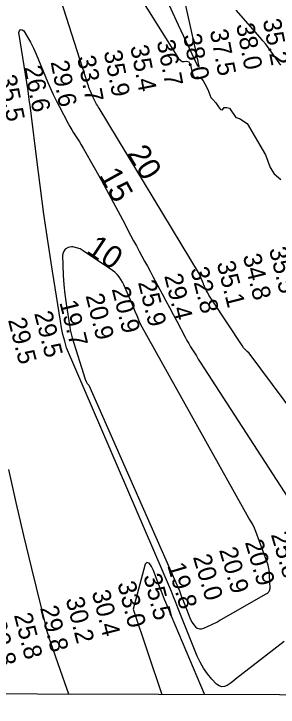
# Model space of a CAD drawing. Extents: x 3161665 to 3199565, y 885729 to 911164.
# Drawn here: x 3179674 to 3180653, y 891109 to 893674 of the extents above; entities that cross this region are included whole.
import ezdxf

# ---------------------------------------------------------------- set-up
doc = ezdxf.new("R2010")
doc.units = 0
for name, color, linetype in [('V-GRID-FRAM', 7, 'Continuous'), ('V-RIVR-RANG', 7, 'Continuous'), ('V-SITE-VEGE', 7, 'Continuous'), ('V-TOPO-DPTH', 7, 'Continuous'), ('V-TOPO-MAJR', 7, 'Continuous'), ('V-TOPO-MINR', 7, 'Continuous'), ('V-TOPO-MINR-IDEN', 7, 'Continuous'), ('V-WETL-SWMP', 7, 'Continuous')]:
    doc.layers.add(name, color=color, linetype=linetype)

msp = doc.modelspace()

# ---------------------------------------------------------------- linework, layer by layer
at = {"layer": 'V-GRID-FRAM'}
msp.add_lwpolyline([(3165935.6, 909383.8), (3197271.3, 909297.2), (3197229, 891108.8), (3165877.4, 891195.5), (3165935.6, 909383.8)], dxfattribs=at)
at = {"layer": 'V-SITE-VEGE'}
for p, q in [((3180093.9, 893811.8), (3180283.7, 893509.1)), ((3180283.7, 893509.1), (3180293.5, 893500.4)), ((3180293.5, 893500.4), (3180297.8, 893498.2)), ((3180297.8, 893498.2), (3180304.3, 893498.2)), ((3180304.3, 893498.2), (3180313, 893499.3)), ((3180313, 893499.3), (3180321.7, 893496)), ((3180321.7, 893496), (3180328.2, 893484.1)), ((3180328.2, 893484.1), (3180331.4, 893467.8)), ((3180331.4, 893467.8), (3180338, 893445)), ((3180338, 893445), (3180343.4, 893437.4)), ((3180343.4, 893437.4), (3180354.2, 893440.7)), ((3180354.2, 893440.7), (3180365.1, 893438.5)), ((3180365.1, 893438.5), (3180374.8, 893425.5)), ((3180374.8, 893425.5), (3180381.3, 893414.6)), ((3180381.3, 893414.6), (3180392.2, 893394)), ((3180392.2, 893394), (3180403, 893364.7)), ((3180403, 893364.7), (3180410.6, 893357.1)), ((3180410.6, 893357.1), (3180422.6, 893344.1)), ((3180422.6, 893344.1), (3180432.3, 893330)), ((3180432.3, 893330), (3180438.8, 893320.2)), ((3180446.4, 893319.2), (3180452.9, 893327.8)), ((3180452.9, 893327.8), (3180462.7, 893327.8)), ((3180462.7, 893327.8), (3180472.5, 893324.6)), ((3180438.8, 893320.2), (3180446.4, 893319.2)), ((3180472.5, 893324.6), (3180496.3, 893290.9)), ((3180496.3, 893290.9), (3180509.4, 893286.6)), ((3180509.4, 893286.6), (3180538.1, 893268)), ((3180538.1, 893268), (3180606.4, 893152.6)), ((3180606.4, 893152.6), (3180623.5, 893105.6)), ((3180623.5, 893105.6), (3180638.5, 893082.1)), ((3180638.5, 893082.1), (3180662, 893060.7))]:
    msp.add_line(p, q, dxfattribs=at)
at = {"layer": 'V-TOPO-DPTH'}
msp.add_lwpolyline([(3179885, 892494.7), (3179887.6, 892484.8), (3179890.4, 892475), (3179938.7, 892322.2), (3179942.1, 892314.1), (3179946.2, 892306.6), (3179951.5, 892299.8), (3180287.6, 891539.2), (3180290.2, 891531.8), (3180292.8, 891524.5), (3180295.5, 891517.3), (3180298.3, 891510), (3180325.6, 891439.3), (3180329.7, 891430.4), (3180334.4, 891421.8), (3180340.1, 891413.9), (3180346.3, 891406.3), (3180353.5, 891401.2), (3180361.1, 891398.2), (3180369.2, 891398.3), (3180377.7, 891400.4), (3180425.3, 891423.3), (3180429.5, 891425.5), (3180433.5, 891427.8), (3180437.4, 891430.3), (3180441.3, 891433), (3180607.9, 891528.5), (3180611, 891529.8), (3180614, 891531.5), (3180616.5, 891533.8), (3180618.7, 891536.4), (3180620.4, 891539.4), (3180621.6, 891542.6), (3180622.3, 891545.9), (3180622.5, 891549.4), (3180621.2, 891595.7), (3180620.2, 891608.8), (3180618.4, 891621.8), (3180615.2, 891634.5), (3180611.3, 891647.1), (3180569.9, 891758.7), (3180564.6, 891771.6), (3180558.6, 891784.2), (3180551.7, 891796.4), (3180544.2, 891808.2), (3180142.8, 892525.3), (3180136.7, 892541.1), (3180130.4, 892556.8), (3180124, 892572.5), (3180117.4, 892588.1), (3180086.3, 892660.5), (3180081.4, 892671), (3180076.1, 892681.3), (3180070.2, 892691.2), (3180063.8, 892700.9), (3180056.6, 892709.8), (3180048.7, 892717.9), (3180039.7, 892724.8), (3179931.6, 892797), (3179919.8, 892804.3), (3179906.7, 892808.8), (3179892.7, 892811.5), (3179888.4, 892811.8), (3179875.2, 892809.2), (3179864.8, 892803.6), (3179858.6, 892793.6), (3179855.1, 892780.7), (3179855.6, 892743.1), (3179856.8, 892707.4), (3179859, 892671.8), (3179862.8, 892636.4), (3179867.6, 892601), (3179881.1, 892514.7), (3179882.9, 892504.6), (3179885, 892494.7)], dxfattribs=at)
at = {"layer": 'V-TOPO-MAJR'}
for points in [[(3180209, 894161.2), (3180349, 893526.9), (3180350.6, 893519.5), (3180352.3, 893512), (3180353.9, 893504.5), (3180355.6, 893497), (3180358.4, 893484.2), (3180358.6, 893483.1), (3180358.6, 893479.9), (3180358.2, 893477.1), (3180358, 893476.9)], [(3180358, 893476.9), (3180357.9, 893476.8), (3180357.8, 893476.8), (3180357.6, 893476.9), (3180357.3, 893477.2), (3180355, 893481.3), (3180354.6, 893482.1), (3180354.2, 893482.9), (3180283.4, 893631.5), (3180249.6, 893707.4)]]:
    msp.add_lwpolyline(points, dxfattribs=at)
at = {"layer": 'V-TOPO-MINR'}
for points in [[(3181020.6, 891780.5), (3180544.9, 892418.5), (3180537.8, 892424.8), (3180531, 892431.5), (3180524.9, 892438.8), (3180519.3, 892446.5), (3180410.3, 892610.3), (3180405.4, 892617.8), (3180400.7, 892625.5), (3180396.2, 892633.4), (3180391.8, 892641.3), (3180387.7, 892649.3), (3180383.8, 892657.5), (3180380.1, 892665.7), (3180376.6, 892674), (3180376.3, 892675), (3180372.7, 892683.9), (3180369, 892692.7), (3180365.2, 892701.5), (3180361.4, 892710.2), (3179989.9, 893325.5), (3179986.8, 893330.1), (3179983.7, 893334.8), (3179980.8, 893339.5), (3179977.9, 893344.3), (3179975.1, 893349.2), (3179972.5, 893354.1), (3179970.1, 893359.2), (3179967.8, 893364.3), (3179957, 893389.9), (3179954.7, 893395.7), (3179952.4, 893401.5), (3179950.3, 893407.3), (3179948.4, 893413.3), (3179820.1, 893816)], [(3180674.6, 891351.6), (3180494.7, 891212.8), (3180485.1, 891204.2), (3180474.9, 891196.4), (3180464.3, 891189), (3180453.8, 891185.3), (3180443.7, 891184.4), (3180434.1, 891187.8), (3180424.9, 891194), (3180407.6, 891212.7), (3180391.3, 891232.3), (3180376.6, 891252.8), (3180364.3, 891274.9), (3180353.5, 891298), (3180281.9, 891475.7), (3180273.8, 891496.1), (3180265.9, 891516.5), (3180258.2, 891537.1), (3179869.9, 892438.1), (3179862.7, 892462.7), (3179856.3, 892487.4), (3179851, 892512.4), (3179846.5, 892537.5), (3179817.5, 892721.4), (3179801.4, 892827.2), (3179786, 892933.1), (3179771.7, 893039.1), (3179758.2, 893145.3), (3179739.8, 893295), (3179735.8, 893326.3), (3179731.6, 893357.6), (3179727, 893388.9), (3179722.3, 893420.1), (3179693.1, 893604.7), (3179695.8, 893611.7), (3179699.6, 893615.8), (3179705.1, 893615.3), (3179711.8, 893611.7), (3179724.3, 893590.7), (3179736.2, 893569.3), (3179746.9, 893547.3), (3179756.8, 893524.9), (3179800.2, 893419.7), (3179809.8, 893397.5), (3179819.8, 893375.4), (3179830.5, 893353.6), (3179841.6, 893332.1), (3179875.7, 893268.2), (3179882.1, 893256.6), (3179888.7, 893245.1), (3179895.6, 893233.8), (3179902.7, 893222.7), (3179909.9, 893211.5), (3179916.9, 893200.3), (3179923.7, 893188.9), (3179930.4, 893177.4), (3179971.6, 893105.4), (3179998.4, 893057.7), (3180024.9, 893009.8), (3180050.9, 892961.6), (3180076.5, 892913.3), (3180107.9, 892853.1), (3180117.9, 892834.2), (3180127.9, 892815.3), (3180138.1, 892796.5), (3180148.3, 892777.7), (3180158.6, 892759), (3180168.8, 892740.2), (3180178.9, 892721.4), (3180189, 892702.5), (3180223.5, 892637.8), (3180236.9, 892612.5), (3180250.3, 892587.3), (3180263.8, 892562), (3180277.2, 892536.8), (3180308.7, 892477.6), (3180315.2, 892465.8), (3180321.8, 892454.1), (3180328.7, 892442.5), (3180335.8, 892431.1), (3180343, 892419.7), (3180350, 892408.3), (3180357, 892396.7), (3180363.9, 892385.2), (3180744.9, 891797.1)], [(3179885, 892494.7), (3179887.6, 892484.8), (3179890.4, 892475), (3179938.7, 892322.2), (3179942.1, 892314.1), (3179946.2, 892306.6), (3179951.5, 892299.8), (3180287.6, 891539.2), (3180290.2, 891531.8), (3180292.8, 891524.5), (3180295.5, 891517.3), (3180298.3, 891510), (3180325.6, 891439.3), (3180329.7, 891430.4), (3180334.4, 891421.8), (3180340.1, 891413.9), (3180346.3, 891406.3), (3180353.5, 891401.2), (3180361.1, 891398.2), (3180369.2, 891398.3), (3180377.7, 891400.4), (3180425.3, 891423.3), (3180429.5, 891425.5), (3180433.5, 891427.8), (3180437.4, 891430.3), (3180441.3, 891433), (3180607.9, 891528.5), (3180611, 891529.8), (3180614, 891531.5), (3180616.5, 891533.8), (3180618.7, 891536.4), (3180620.4, 891539.4), (3180621.6, 891542.6), (3180622.3, 891545.9), (3180622.5, 891549.4), (3180621.2, 891595.7), (3180620.2, 891608.8), (3180618.4, 891621.8), (3180615.2, 891634.5), (3180611.3, 891647.1), (3180569.9, 891758.7), (3180564.6, 891771.6), (3180558.6, 891784.2), (3180551.7, 891796.4), (3180544.2, 891808.2), (3180142.8, 892525.3), (3180136.7, 892541.1), (3180130.4, 892556.8), (3180124, 892572.5), (3180117.4, 892588.1), (3180086.3, 892660.5), (3180081.4, 892671), (3180076.1, 892681.3), (3180070.2, 892691.2), (3180063.8, 892700.9), (3180056.6, 892709.8), (3180048.7, 892717.9), (3180039.7, 892724.8), (3179931.6, 892797), (3179919.8, 892804.3), (3179906.7, 892808.8), (3179892.7, 892811.5), (3179888.4, 892811.8), (3179875.2, 892809.2), (3179864.8, 892803.6), (3179858.6, 892793.6), (3179855.1, 892780.7), (3179855.6, 892743.1), (3179856.8, 892707.4), (3179859, 892671.8), (3179862.8, 892636.4), (3179867.6, 892601), (3179881.1, 892514.7), (3179882.9, 892504.6), (3179885, 892494.7)], [(3179878.4, 891156.8), (3179870.5, 891177.9), (3179846.7, 891244.3), (3179810, 891350.1), (3179805.4, 891364), (3179801.1, 891377.9), (3179797.1, 891392), (3179793.5, 891406.1), (3179740.8, 891621.4), (3179711.6, 891743.4), (3179683.2, 891865.5), (3179656.1, 891988)], [(3180380.6, 891155.4), (3180380.1, 891156.4), (3180257.6, 891445.8), (3180245, 891476.2), (3180232.6, 891506.6), (3180220.5, 891537.2), (3180208.6, 891567.9), (3180190.7, 891614.8), (3180187.6, 891621.9), (3180184, 891628.6), (3180179.7, 891634.9), (3180175, 891641), (3180170.8, 891643.1), (3180166.9, 891643.6), (3180163.7, 891641.5), (3180160.8, 891637.7), (3180115.9, 891471.8)], [(3180115.9, 891471.8), (3180222.1, 891155.8)]]:
    msp.add_lwpolyline(points, dxfattribs=at)
at = {"layer": 'V-WETL-SWMP'}
msp.add_lwpolyline([(3180662.7, 893483.5), (3180625.8, 893536.3), (3180606.5, 893562), (3180596.4, 893574.6), (3180585.8, 893586.9), (3180496.9, 893687.2)], dxfattribs=at)

# ---------------------------------------------------------------- texts
at = {"layer": 'V-RIVR-RANG'}
for s, rotation, p in [('38.0', 281.0883, (3180496.6, 893633.5)), ('35.2', 281.0883, (3180595.3, 893650.1)), ('37.5', 281.0883, (3180399.1, 893611.2)), ('38.0', 281.0883, (3180300.5, 893594.6)), ('35.4', 281.0883, (3180104.9, 893552.8)), ('36.7', 281.0883, (3180202.9, 893572.2)), ('35.9', 281.0883, (3180006.7, 893533.6)), ('33.7', 281.0883, (3179908.7, 893513.8)), ('26.6', 281.0883, (3179712.2, 893476.7)), ('29.6', 281.0883, (3179810.2, 893496.2)), ('35.5', 281.3703, (3179616.5, 893442)), ('35.5', 284.0783, (3180618.2, 892803.1)), ('34.8', 284.0783, (3180521.3, 892778.5)), ('32.8', 284.0783, (3180327.4, 892729.4)), ('35.1', 284.0783, (3180424.9, 892751.6)), ('29.4', 284.0783, (3180230.5, 892704.8)), ('25.9', 284.0783, (3180133.5, 892680.5)), ('20.9', 284.0783, (3180036.5, 892655.9)), ('20.9', 284.0783, (3179939.6, 892631.3)), ('19.7', 284.0783, (3179842.7, 892606.5)), ('29.5', 284.3656, (3179749.2, 892566)), ('29.5', 284.3656, (3179652.3, 892541.5)), ('25.8', 286.4583, (3180625.1, 891747.6)), ('20.9', 286.4583, (3180529.2, 891719.2)), ('20.9', 286.4583, (3180433.4, 891690.7)), ('20.0', 286.4583, (3180336.8, 891664.6)), ('19.8', 286.4583, (3180241.8, 891633.3)), ('35.5', 284.2928, (3180153.3, 891594.1)), ('33.0', 284.2928, (3180057.3, 891566.3)), ('30.4', 284.2928, (3179962.3, 891534.1)), ('30.2', 284.2928, (3179865.8, 891508.4)), ('29.8', 284.2928, (3179770.9, 891476.2)), ('25.8', 284.2928, (3179674.5, 891449.7)), ('23.8', 284.2928, (3179578.3, 891422.7))]:
    msp.add_text(s, height=67, rotation=rotation, dxfattribs=at).set_placement(p)
at = {"layer": 'V-TOPO-MINR-IDEN'}
for s, rotation, p in [('20', 301.1227, (3180091.3, 893157.5)), ('15', 298.9738, (3179987.7, 893077.2)), ('10', 326.244, (3179938.2, 892792.6))]:
    msp.add_text(s, height=83, rotation=rotation, dxfattribs=at).set_placement(p)

doc.saveas('drawing.dxf')
